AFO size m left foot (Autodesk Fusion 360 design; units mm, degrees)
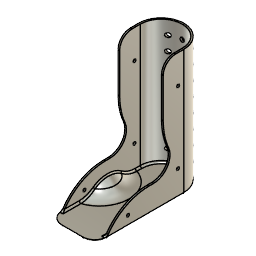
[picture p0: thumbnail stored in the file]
part number: 2025-10-02-12-56-12-317
sketch "Sketch1" plane through (0, 0, 0) normal (0, 0, 1) x axis (1, 0, 0)
  line L1 (-27.4, -108) -> (-27.4, 0)
  line L2 (27.4, -108) -> (-27.4, -108)
  line L3 (27.4, 0) -> (27.4, -108)
  line L4 (-25.4, 0) -> (-25.4, -108)
  line L5 (25.4, 0) -> (25.4, -108)
  line L6 (-25.4, 0) -> (-27.4, 0)
  line L7 (27.4, 0) -> (25.4, 0)
  line L8 (-25.4, -93) -> (-27.4, -93)
  line L9 (-12.4, -108) -> (-12.4, -93)
  line L10 (12.4, -108) -> (12.4, -93)
  line L11 (12.4, -108) -> (-12.4, -108)
  line L12 (27.8748, -92.9999) -> (-13.1252, -92.9999)
  circle C1 centre (0, 0) radius 27.4
  circle C2 centre (0, 0) radius 25.4
  circle C3 centre (-12.4, -93) radius 15
  circle C4 centre (12.4, -93) radius 15
  circle C5 centre (-12.4, -93) radius 13
  circle C6 centre (12.4, -93) radius 13
  point P1 (0, 0)
  point P2 (0, 0)
  point P3 (-27.4, 0)
  point P6 (27.4, 0)
  point P7 (0, 0)
  point P8 (-25.4, 0)
  point P10 (25.4, 0)
  point P11 (25.4, -108)
  point P9 (-25.4, -108)
  point P16 (-27.4, -93)
  point P17 (-25.4, -93)
  point P12 (-12.4, -93)
  point P18 (-12.4, -93)
  point P19 (-12.4, -108)
  point P15 (12.4, -93)
  point P20 (12.4, -93)
  point P21 (12.4, -108)
  coincident P1 P2
  coincident C1 P3
  tangent C1 L1
  vertical L1
  perpendicular L1 L2
  coincident C1 P6
  tangent C1 L3
  perpendicular L2 L3
  coincident P1 P7
  vertical L4
  coincident C2 P8
  vertical L5
  coincident C2 P10
  perpendicular L4 L6
  perpendicular L3 L7
  coincident L2 P11
  coincident L2 P9
  tangent L3 C4
  tangent L1 C3
  tangent L2 C3
  tangent L2 C4
  concentric C3 C5
  tangent L4 C5
  concentric C4 C6
  tangent L5 C6
  coincident C3 P16
  coincident C5 P17
  coincident L4 P17
  perpendicular L4 L8
  coincident P12 P18
  coincident L2 P19
  coincident C3 P19
  perpendicular L2 L9
  coincident P15 P20
  coincident L2 P21
  coincident C4 P21
  perpendicular L2 L10
  perpendicular L3 L12
  dimension "d2" diameter C1 = 54.8 (= "d57 + ( 2 * 2 ) * 1 mm")
  dimension "d4" distance P2 L2 = 108
  dimension "d57" diameter C2 = 50.8
  dimension "d73" diameter C3 = 30
  dimension "d74" diameter C4 = 30
extrude "Extrude1" new body sketch "Sketch1" profile of C1 L1 L3 L4 L5 L6 L7 C3 C4 L8 L12 along normal blind 30
extrude "Extrude2" add sketch "Sketch1" profile of C1 C2 L4 L5 C3 C4 C5 C6 L8 L9 L10 L12 along normal blind 2
extrude "Extrude8" add sketch "Sketch1" profile of L2 C3 C4 L11 along normal blind 2
extrude "Extrude3" add sketch "Sketch1" profile of C1 C2 L6 L7 along normal blind 152.4
work_plane "WorkPlane3" AlongDistance 40
sphere_primitive "SpherePrimitive3" Diameter 55
move_face "MoveFace3"
boundary_fill "BoundaryFill2"
offset_faces "OffsetFaces3" distance 2
shell "Shell5" innerThickness 2
mirror "Mirror2" mirrorStitchTolerance 0.1
extrude "Extrude16" cut of existing geometry blind -25
delete_face "DeleteFace1"
delete_face "DeleteFace2"
fillet "Fillet31" radius 25
work_plane "WorkPlane1" RotateAngle -90
sketch "Sketch2" plane through (27.4, 0, 0) normal (1, 0, 0) x axis (0, 1, 0)
  line L1 (0, 152.4) -> (-25, 152.4)
  line L2 (0, 30) -> (0, 152.4)
  line L3 (-25, 62.4) -> (-25, 152.4)
  line L4 (0, 30) -> (-25, 62.4)
  circle C1 centre (-7, 117.4) radius 1.75
  point P2 (0, 30)
  point P6 (0, 30)
  point P4 (0, 152.4)
  point P7 (0, 152.4)
  point P3 (-25, 152.4)
  point P5 (-25, 62.4)
  point P8 (-7, 117.4)
  horizontal L1
  perpendicular L1 L2
  perpendicular L1 L3
  coincident P2 P6
  coincident P4 P7
  dimension "d25" distance P3 P4 = 25
  dimension "d28" distance P3 P5 = 90
  dimension "d43" diameter C1 = 3.5
  dimension "d45" distance L3 P8 = 18
  dimension "d47" distance L1 P8 = 35
extrude "Extrude11" add sketch "Sketch2" against normal blind 2
mirror "Mirror1" mirrorStitchTolerance 0.1
work_plane "WorkPlane4" AlongDistance 24.25
sketch "Sketch9" plane through (0, 24.25, 0) normal (0, 1, 0) x axis (1, 0, 0)
  circle C1 centre (0, -17) radius 2.5
  circle C2 centre (0, -34) radius 2.5
  circle C3 centre (0, -51) radius 2.5
  circle C4 centre (0, -68) radius 2.5
  circle C5 centre (0, -102) radius 2.5
  circle C6 centre (0, -85) radius 2.5
  circle C7 centre (0, -136) radius 2.5
  circle C8 centre (0, -119) radius 2.5
  point P2 (0, -17)
  point P8 (0, 0)
  point P3 (0, -34)
  point P4 (0, -51)
  point P5 (0, -68)
  point P7 (0, -85)
  point P6 (0, -102)
  dimension "d123" diameter C1 = 5
  dimension "d124" diameter C2 = 5
  dimension "d125" diameter C3 = 5
  dimension "d126" diameter C4 = 5
  dimension "d127" diameter C5 = 5
  dimension "d128" diameter C6 = 5
  dimension "d129" distance P2 P8 = 17
  dimension "d130" distance P2 P3 = 17
  dimension "d131" distance P3 P4 = 17
  dimension "d132" distance P4 P5 = 17 (= "d131")
  dimension "d133" distance P5 P7 = 17 (= "d131")
  dimension "d134" distance P6 P7 = 17 (= "d131")
  dimension "d183" diameter C7 = 5
  dimension "d184" diameter C8 = 5
extrude "Extrude12" cut sketch "Sketch9" along normal blind 70
path_pattern "PathPattern2" PathPatternDelta 82
fillet "Fillet28" radius 60
fillet "Fillet18" radius 80
fillet "Fillet34" radius 20
fillet "Fillet35" radius 15
fillet "Fillet37" radius 5
fillet "Fillet36" radius 2
hole "Hole3" HoleDepth 90 HoleDiameter 3.5 TipAngle 118
hole "Hole4" HoleDepth 90 HoleDiameter 3.5 TipAngle 118
fillet "Fillet46" radius 10
fillet "Fillet47" radius 10
fillet "Fillet48" radius 2
fillet "Fillet49" radius 2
